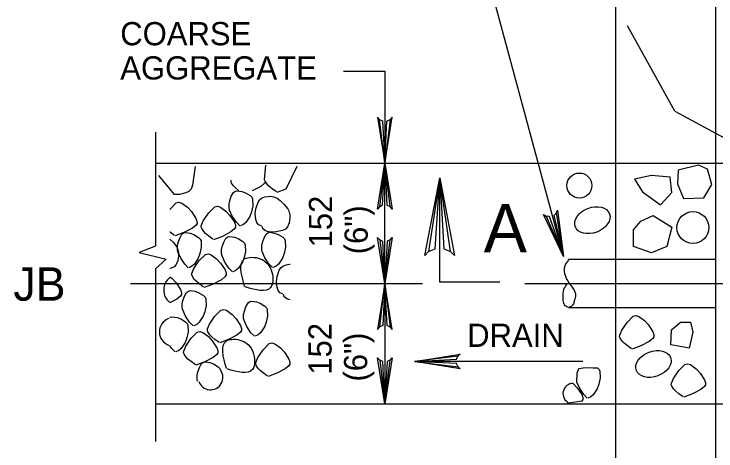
# Model space of a CAD drawing. Extents: x 638455 to 640199, y 298558 to 299152.
# Drawn here: x 638508.8 to 638610.5, y 298960.7 to 299024 of the extents above; entities that cross this region are included whole.
import ezdxf

# ---------------------------------------------------------------- set-up
doc = ezdxf.new("R2010")
doc.units = 0
for name, color, linetype in [('1', 7, 'Continuous'), ('2', 7, 'Continuous'), ('3', 7, 'Continuous')]:
    doc.layers.add(name, color=color, linetype=linetype)

msp = doc.modelspace()

# ---------------------------------------------------------------- linework, layer by layer
at = {"layer": '1'}
for p, q in [((638588.37, 298988.92), (638577.2, 299030.38)), ((638604.5, 299009.98), (638597.64, 299022.33))]:
    msp.add_line(p, q, dxfattribs=at)
for points in [[(638607.93, 299002.12), (638604.99, 299001.42), (638604.91, 298999.41), (638605.77, 298997.32), (638608.71, 298997.39), (638609.87, 298999.33), (638609.25, 299001.58)], [(638602.45, 298996.4), (638604.08, 298998.18), (638603.85, 299000.42), (638601.14, 299000.65), (638598.66, 299000.11), (638599.82, 298998.25)], [(638598.5, 298990.37), (638598.5, 298992.77), (638599.58, 298994.01), (638601.36, 298994.86), (638604.07, 298993.16), (638603.37, 298990.37), (638601.13, 298989.44)], [(638603.93, 298976.13), (638604.02, 298978.28), (638605.31, 298979.4), (638606.77, 298979.4), (638607.12, 298977.94), (638606.6, 298975.62)]]:
    msp.add_lwpolyline(points, close=True, dxfattribs=at)
for centre, radius in [((638590.69, 298999.19), 1.81), ((638607.13, 298993.1), 2.31)]:
    msp.add_circle(centre, radius, dxfattribs=at)
for centre, radius, start, end in [((638532.79, 298984.05), 2.3, 128.3504, 231.6496), ((638531.92, 298978), 2.06, 110.8458, 251.6988), ((638537.27, 298971.41), 1.8, 199.608, 34.7802), ((638589.8, 298969.04), 1.49, 89.5919, 244.8137)]:
    msp.add_arc(centre, radius, start, end, dxfattribs=at)
for centre in [(638592.57, 298994.17), (638601.42, 298973.35)]:
    msp.add_ellipse(centre, major_axis=(-2.48, -0.93), ratio=0.690668, dxfattribs=at)
at = {"layer": '2'}
for p, q in [((638595.94, 299046), (638595.94, 298932.33)), ((638610.47, 298943.57), (638610.47, 299045.2)), ((638556.51, 299015.76), (638562.52, 299015.76)), ((638562.52, 299015.76), (638562.52, 299002.44)), ((638604.5, 299009.98), (638635.74, 298993.07)), ((638529.3, 299006.9), (638529.3, 298990.39)), ((638529.3, 299002.44), (638688.53, 299002.44)), ((638562.52, 298985.02), (638562.52, 299002.44)), ((638570.46, 298985.18), (638570.46, 299000.3)), ((638589.16, 298988.5), (638610.47, 298988.5)), ((638529.3, 298987.13), (638529.3, 298962.13)), ((638525.67, 298985.02), (638567.99, 298985.02)), ((638562.52, 298985.02), (638562.52, 298967.59)), ((638579.18, 298985.18), (638570.46, 298985.18)), ((638582.78, 298985.02), (638777.13, 298985.02)), ((638589.16, 298981.53), (638610.47, 298981.53)), ((638529.3, 298967.59), (638688.53, 298967.59))]:
    msp.add_line(p, q, dxfattribs=at)
for points in [[(638561.72, 299008.77), (638562.18, 299008.54), (638562.52, 299002.44), (638561.72, 299008.77), (638561.45, 299009.1), (638562.52, 299002.44), (638562.82, 299008.53), (638563.27, 299008.75), (638562.52, 299002.44), (638563.58, 299009.1), (638563.27, 299008.75)], [(638545.11, 299000.02), (638545.29, 299002.12)], [(638561.72, 298996.11), (638562.18, 298996.35), (638562.52, 299002.44), (638561.72, 298996.11), (638561.45, 298995.78), (638562.52, 299002.44), (638562.82, 298996.35), (638563.27, 298996.13), (638562.52, 299002.44), (638563.58, 298995.78), (638563.27, 298996.13)], [(638535.06, 299001.95), (638534.68, 298999.23)], [(638549.76, 299001.95), (638548.18, 298998.68)], [(638532.06, 298997.9), (638529.81, 299000.65)], [(638540.26, 298999.77), (638540.26, 298999.98)], [(638545.17, 298999.8), (638545.11, 299000.02)], [(638568.85, 298989.61), (638569.78, 298990), (638570.46, 299000.3), (638568.85, 298989.61), (638568.29, 298989.06), (638570.46, 299000.3), (638571.07, 298990.01), (638572, 298989.63), (638570.46, 299000.3), (638572.61, 298989.06), (638572, 298989.63)], [(638534.68, 298999.23), (638534.45, 298998.66)], [(638540.31, 298999.55), (638540.26, 298999.77)], [(638540.6, 298999.12), (638540.31, 298999.55)], [(638540.89, 298998.83), (638540.6, 298999.12)], [(638544.54, 298999.07), (638543.32, 298998.43)], [(638545.07, 298999.51), (638544.54, 298999.07)], [(638545.22, 298999.76), (638545.07, 298999.51)], [(638545.46, 298999.37), (638545.17, 298999.8)], [(638545.74, 298999.08), (638545.46, 298999.37)], [(638546.19, 298998.71), (638545.74, 298999.08)], [(638533.72, 298998.13), (638532.79, 298997.91)], [(638534.13, 298998.34), (638533.72, 298998.13)], [(638534.45, 298998.66), (638534.13, 298998.34)], [(638540.28, 298997.63), (638540.58, 298998.18)], [(638540.58, 298998.18), (638540.83, 298998.37)], [(638540.83, 298998.37), (638541.14, 298998.44)], [(638541.34, 298998.46), (638540.89, 298998.83)], [(638541.14, 298998.44), (638541.81, 298998.34)], [(638541.81, 298998.34), (638542.34, 298998.14)], [(638542.34, 298998.14), (638543.02, 298997.72)], [(638546.81, 298998.26), (638546.19, 298998.71)], [(638548.18, 298998.68), (638546.89, 298998.2)], [(638532.79, 298997.91), (638532.06, 298997.9)], [(638539.95, 298996.52), (638540.05, 298996.98)], [(638540.05, 298996.98), (638540.28, 298997.63)], [(638543.02, 298997.72), (638543.25, 298997.48)], [(638543.25, 298997.48), (638543.37, 298997.25)], [(638543.37, 298997.25), (638543.4, 298996.27)], [(638544.15, 298996.76), (638544.38, 298997.11)], [(638544.38, 298997.11), (638544.65, 298997.34)], [(638544.65, 298997.34), (638545.15, 298997.54)], [(638545.15, 298997.54), (638545.6, 298997.62)], [(638545.6, 298997.62), (638545.95, 298997.63)], [(638545.95, 298997.63), (638546.46, 298997.56)], [(638546.46, 298997.56), (638546.9, 298997.37)], [(638546.9, 298997.37), (638547.35, 298997.04)], [(638547.35, 298997.04), (638547.96, 298996.46)], [(638531.43, 298995.78), (638532.31, 298996.66)], [(638532.31, 298996.66), (638532.7, 298996.77)], [(638532.7, 298996.77), (638533.13, 298996.64)], [(638533.13, 298996.64), (638533.93, 298996.04)], [(638533.93, 298996.04), (638534.51, 298995.41)], [(638537.01, 298995.22), (638537.88, 298996.1)], [(638537.88, 298996.1), (638538.28, 298996.21)], [(638538.28, 298996.21), (638538.7, 298996.07)], [(638538.7, 298996.07), (638539.51, 298995.48)], [(638539.95, 298995.94), (638539.95, 298996.52)], [(638540.02, 298995.64), (638539.95, 298995.94)], [(638543.4, 298996.27), (638543.21, 298995.38)], [(638543.84, 298995.82), (638544.15, 298996.76)], [(638547.96, 298996.46), (638548.48, 298995.79)], [(638531.4, 298995.73), (638531.43, 298995.78)], [(638534.51, 298995.41), (638535.16, 298994.43)], [(638536.22, 298994.09), (638537.01, 298995.22)], [(638539.51, 298995.48), (638540.08, 298994.85)], [(638540.43, 298994.74), (638540.02, 298995.64)], [(638543.21, 298995.38), (638542.96, 298994.71)], [(638543.76, 298995.12), (638543.84, 298995.82)], [(638543.83, 298994.25), (638543.76, 298995.12)], [(638548.48, 298995.79), (638548.62, 298995.51)], [(638548.62, 298995.51), (638548.76, 298994.92)], [(638548.76, 298994.92), (638548.76, 298994.46)], [(638587.36, 298995.21), (638586.99, 298994.86), (638588.37, 298988.92), (638587.36, 298995.21), (638587.54, 298995.6), (638588.37, 298988.92), (638586.38, 298994.68), (638585.88, 298994.76), (638588.37, 298988.92), (638585.49, 298995.01), (638585.88, 298994.76)], [(638535.16, 298994.43), (638535.31, 298994.02)], [(638535.31, 298994.02), (638535.32, 298993.71)], [(638535.94, 298993.37), (638536.22, 298994.09)], [(638540.08, 298994.85), (638540.73, 298993.87)], [(638541.01, 298993.86), (638540.43, 298994.74)], [(638540.73, 298993.87), (638540.89, 298993.45)], [(638541.51, 298993.34), (638541.01, 298993.86)], [(638542.4, 298993.85), (638542.04, 298993.54)], [(638542.96, 298994.71), (638542.4, 298993.85)], [(638543.97, 298993.84), (638543.83, 298994.25)], [(638548.76, 298994.46), (638548.65, 298993.78)], [(638534.64, 298993.02), (638533.43, 298992.39)], [(638535.17, 298993.46), (638534.64, 298993.02)], [(638535.32, 298993.71), (638535.17, 298993.46)], [(638535.93, 298993.16), (638535.94, 298993.37)], [(638535.99, 298992.94), (638535.93, 298993.16)], [(638536.28, 298992.51), (638535.99, 298992.94)], [(638540.75, 298992.9), (638540.21, 298992.46)], [(638540.89, 298993.15), (638540.75, 298992.9)], [(638540.89, 298993.45), (638540.89, 298993.15)], [(638542.04, 298993.54), (638541.63, 298993.34)], [(638544.22, 298993.5), (638543.97, 298993.84)], [(638544.65, 298993.34), (638544.22, 298993.5)], [(638544.87, 298992.9), (638544.73, 298993.29)], [(638545.22, 298992.64), (638544.87, 298992.9)], [(638548.11, 298992.89), (638547.69, 298992.67)], [(638548.42, 298993.21), (638548.11, 298992.89)], [(638548.65, 298993.78), (638548.42, 298993.21)], [(638531.44, 298992.42), (638531.4, 298992.45)], [(638532.05, 298991.97), (638531.44, 298992.42)], [(638533.43, 298992.39), (638532.14, 298991.91)], [(638532.82, 298991.58), (638533.11, 298992.13)], [(638533.11, 298992.13), (638533.36, 298992.33)], [(638533.36, 298992.33), (638533.67, 298992.39)], [(638533.67, 298992.39), (638534.34, 298992.29)], [(638534.34, 298992.29), (638534.87, 298992.09)], [(638534.87, 298992.09), (638535.55, 298991.67)], [(638536.56, 298992.22), (638536.28, 298992.51)], [(638537.01, 298991.85), (638536.56, 298992.22)], [(638537.63, 298991.4), (638537.01, 298991.85)], [(638539, 298991.82), (638537.71, 298991.34)], [(638540.21, 298992.46), (638539, 298991.82)], [(638545.02, 298991.6), (638545.32, 298992.15)], [(638545.53, 298992.52), (638545.22, 298992.64)], [(638545.32, 298992.15), (638545.56, 298992.35)], [(638546.03, 298992.44), (638545.53, 298992.52)], [(638545.56, 298992.35), (638545.87, 298992.41)], [(638545.87, 298992.41), (638546.55, 298992.31)], [(638546.76, 298992.46), (638546.03, 298992.44)], [(638546.55, 298992.31), (638547.07, 298992.11)], [(638547.69, 298992.67), (638546.76, 298992.46)], [(638547.07, 298992.11), (638547.75, 298991.69)], [(638531.4, 298991.44), (638531.85, 298991)], [(638531.85, 298991), (638532.36, 298990.34)], [(638532.48, 298990.47), (638532.58, 298990.93)], [(638532.58, 298990.93), (638532.82, 298991.58)], [(638535.55, 298991.67), (638535.78, 298991.43)], [(638535.78, 298991.43), (638535.9, 298991.2)], [(638535.9, 298991.2), (638535.93, 298990.22)], [(638538.98, 298990.35), (638539.22, 298991)], [(638539.22, 298991), (638539.51, 298991.55)], [(638539.51, 298991.55), (638539.76, 298991.75)], [(638539.76, 298991.75), (638540.07, 298991.81)], [(638540.07, 298991.81), (638540.74, 298991.71)], [(638540.74, 298991.71), (638541.27, 298991.51)], [(638541.27, 298991.51), (638541.95, 298991.09)], [(638541.95, 298991.09), (638542.18, 298990.86)], [(638542.18, 298990.86), (638542.3, 298990.62)], [(638544.69, 298990.49), (638544.78, 298990.95)], [(638544.78, 298990.95), (638545.02, 298991.6)], [(638547.75, 298991.69), (638547.98, 298991.45)], [(638547.98, 298991.45), (638548.1, 298991.22)], [(638548.1, 298991.22), (638548.13, 298990.24)], [(638563.31, 298991.34), (638562.85, 298991.11), (638562.52, 298985.02), (638563.31, 298991.34), (638563.59, 298991.67), (638562.52, 298985.02), (638562.22, 298991.1), (638561.77, 298991.33), (638562.52, 298985.02), (638561.46, 298991.67), (638561.77, 298991.33)], [(638529.3, 298990.39), (638526.92, 298989.48), (638530.85, 298988.51), (638529.3, 298987.13)], [(638532.36, 298990.34), (638532.51, 298990.05)], [(638532.48, 298989.89), (638532.48, 298990.47)], [(638532.55, 298989.6), (638532.48, 298989.89)], [(638532.51, 298990.05), (638532.64, 298989.47)], [(638535.93, 298990.22), (638535.74, 298989.33)], [(638538.88, 298989.9), (638538.98, 298990.35)], [(638538.88, 298989.32), (638538.88, 298989.9)], [(638542.3, 298990.62), (638542.33, 298989.65)], [(638544.68, 298989.91), (638544.69, 298990.49)], [(638544.75, 298989.62), (638544.68, 298989.91)], [(638548.13, 298990.24), (638547.95, 298989.35)], [(638532.65, 298989), (638532.54, 298988.32)], [(638532.96, 298988.69), (638532.55, 298989.6)], [(638532.64, 298989.47), (638532.65, 298989)], [(638535.74, 298989.33), (638535.49, 298988.66)], [(638535.65, 298988.31), (638536.53, 298989.19)], [(638536.53, 298989.19), (638536.92, 298989.3)], [(638536.92, 298989.3), (638537.35, 298989.16)], [(638537.35, 298989.16), (638538.15, 298988.56)], [(638538.95, 298989.02), (638538.88, 298989.32)], [(638539.36, 298988.11), (638538.95, 298989.02)], [(638542.33, 298989.65), (638542.14, 298988.75)], [(638545.16, 298988.71), (638544.75, 298989.62)], [(638547.95, 298989.35), (638547.69, 298988.68)], [(638532.31, 298987.75), (638531.99, 298987.43)], [(638532.54, 298988.32), (638532.31, 298987.75)], [(638533.54, 298987.81), (638532.96, 298988.69)], [(638534.04, 298987.29), (638533.54, 298987.81)], [(638534.93, 298987.8), (638534.57, 298987.49)], [(638534.87, 298987.17), (638535.65, 298988.31)], [(638535.49, 298988.66), (638534.93, 298987.8)], [(638538.15, 298988.56), (638538.73, 298987.94)], [(638538.73, 298987.94), (638539.37, 298986.96)], [(638539.94, 298987.23), (638539.36, 298988.11)], [(638541.89, 298988.09), (638541.32, 298987.23)], [(638542.14, 298988.75), (638541.89, 298988.09)], [(638545.74, 298987.83), (638545.16, 298988.71)], [(638546.25, 298987.31), (638545.74, 298987.83)], [(638547.13, 298987.82), (638546.77, 298987.51)], [(638547.69, 298988.68), (638547.13, 298987.82)], [(638548.24, 298987.71), (638548.69, 298987.78)], [(638548.69, 298987.78), (638548.82, 298987.79)], [(638531.58, 298987.22), (638531.4, 298987.18)], [(638531.99, 298987.43), (638531.58, 298987.22)], [(638534.57, 298987.49), (638534.16, 298987.29)], [(638534.58, 298986.46), (638534.87, 298987.17)], [(638539.37, 298986.96), (638539.53, 298986.54)], [(638540.44, 298986.71), (638539.94, 298987.23)], [(638540.97, 298986.91), (638540.55, 298986.71)], [(638541.32, 298987.23), (638540.97, 298986.91)], [(638546.77, 298987.51), (638546.36, 298987.31)], [(638546.93, 298985.99), (638547.23, 298986.92)], [(638547.23, 298986.92), (638547.46, 298987.28)], [(638547.46, 298987.28), (638547.73, 298987.51)], [(638547.73, 298987.51), (638548.24, 298987.71)], [(638531.4, 298985.97), (638531.7, 298985.74)], [(638531.7, 298985.74), (638532.28, 298985.11)], [(638534.57, 298986.25), (638534.58, 298986.46)], [(638534.64, 298986.03), (638534.57, 298986.25)], [(638534.92, 298985.6), (638534.64, 298986.03)], [(638539.39, 298985.99), (638538.86, 298985.54)], [(638539.54, 298986.24), (638539.39, 298985.99)], [(638539.53, 298986.54), (638539.54, 298986.24)], [(638546.85, 298985.29), (638546.93, 298985.99)], [(638532.28, 298985.11), (638532.93, 298984.13)], [(638535.21, 298985.32), (638534.92, 298985.6)], [(638535.66, 298984.95), (638535.21, 298985.32)], [(638536.27, 298984.49), (638535.66, 298984.95)], [(638537.64, 298984.91), (638536.36, 298984.44)], [(638538.86, 298985.54), (638537.64, 298984.91)], [(638546.91, 298984.41), (638546.85, 298985.29)], [(638563.31, 298978.69), (638562.85, 298978.92), (638562.52, 298985.02), (638563.31, 298978.69), (638563.59, 298978.36), (638562.52, 298985.02), (638562.22, 298978.93), (638561.77, 298978.71), (638562.52, 298985.02), (638561.46, 298978.36), (638561.77, 298978.71)], [(638532.93, 298984.13), (638533.08, 298983.71)], [(638533.08, 298983.71), (638533.09, 298983.41)], [(638533.52, 298983.16), (638533.81, 298983.71)], [(638533.81, 298983.71), (638534.06, 298983.91)], [(638534.06, 298983.91), (638534.37, 298983.97)], [(638534.37, 298983.97), (638535.04, 298983.87)], [(638535.04, 298983.87), (638535.57, 298983.67)], [(638547.05, 298984), (638546.91, 298984.41)], [(638547.31, 298983.66), (638547.05, 298984)], [(638532.41, 298982.72), (638531.4, 298982.19)], [(638532.94, 298983.16), (638532.41, 298982.72)], [(638533.09, 298983.41), (638532.94, 298983.16)], [(638533.28, 298982.51), (638533.52, 298983.16)], [(638535.57, 298983.67), (638536.25, 298983.25)], [(638536.25, 298983.25), (638536.48, 298983.02)], [(638536.48, 298983.02), (638536.6, 298982.79)], [(638536.6, 298982.79), (638536.63, 298981.81)], [(638547.73, 298983.51), (638547.31, 298983.66)], [(638547.95, 298983.07), (638547.82, 298983.45)], [(638548.3, 298982.8), (638547.95, 298983.07)], [(638548.62, 298982.69), (638548.3, 298982.8)], [(638548.82, 298982.65), (638548.62, 298982.69)], [(638533.18, 298982.06), (638533.28, 298982.51)], [(638533.18, 298981.48), (638533.18, 298982.06)], [(638536.63, 298981.81), (638536.44, 298980.92)], [(638542.4, 298981.64), (638542.7, 298982.19)], [(638542.7, 298982.19), (638542.95, 298982.38)], [(638542.95, 298982.38), (638543.26, 298982.45)], [(638543.26, 298982.45), (638543.93, 298982.35)], [(638543.93, 298982.35), (638544.46, 298982.15)], [(638544.46, 298982.15), (638545.14, 298981.73)], [(638545.14, 298981.73), (638545.37, 298981.49)], [(638533.25, 298981.18), (638533.18, 298981.48)], [(638533.66, 298980.27), (638533.25, 298981.18)], [(638536.44, 298980.92), (638536.19, 298980.25)], [(638537.89, 298980.27), (638538.77, 298981.15)], [(638538.77, 298981.15), (638539.17, 298981.25)], [(638539.17, 298981.25), (638539.59, 298981.12)], [(638539.59, 298981.12), (638540.39, 298980.52)], [(638542.07, 298980.53), (638542.17, 298980.99)], [(638542.17, 298980.99), (638542.4, 298981.64)], [(638545.37, 298981.49), (638545.49, 298981.26)], [(638545.49, 298981.26), (638545.52, 298980.29)], [(638531.4, 298980.06), (638531.47, 298980.12)], [(638531.47, 298980.12), (638531.78, 298980.18)], [(638531.78, 298980.18), (638532.45, 298980.08)], [(638532.45, 298980.08), (638532.98, 298979.88)], [(638532.98, 298979.88), (638533.66, 298979.46)], [(638534.24, 298979.4), (638533.66, 298980.27)], [(638536.19, 298980.25), (638535.63, 298979.39)], [(638537.11, 298979.13), (638537.89, 298980.27)], [(638540.39, 298980.52), (638540.97, 298979.89)], [(638540.97, 298979.89), (638541.61, 298978.91)], [(638542.07, 298979.95), (638542.07, 298980.53)], [(638542.14, 298979.66), (638542.07, 298979.95)], [(638542.55, 298978.75), (638542.14, 298979.66)], [(638545.52, 298980.29), (638545.33, 298979.39)], [(638597.6, 298979.37), (638598.48, 298980.25)], [(638598.48, 298980.25), (638598.87, 298980.35)], [(638598.87, 298980.35), (638599.3, 298980.22)], [(638599.3, 298980.22), (638600.1, 298979.62)], [(638600.1, 298979.62), (638600.68, 298979)], [(638533.66, 298979.46), (638533.89, 298979.23)], [(638533.89, 298979.23), (638534.01, 298979)], [(638534.01, 298979), (638534.04, 298978.02)], [(638534.74, 298978.87), (638534.24, 298979.4)], [(638535.27, 298979.07), (638534.86, 298978.87)], [(638535.63, 298979.39), (638535.27, 298979.07)], [(638536.83, 298978.41), (638537.11, 298979.13)], [(638541.61, 298978.91), (638541.77, 298978.5)], [(638543.13, 298977.87), (638542.55, 298978.75)], [(638545.08, 298978.72), (638544.52, 298977.86)], [(638545.33, 298979.39), (638545.08, 298978.72)], [(638596.82, 298978.23), (638597.6, 298979.37)], [(638600.68, 298979), (638601.32, 298978.01)], [(638534.04, 298978.02), (638533.85, 298977.13)], [(638534.46, 298977.06), (638535.33, 298977.94)], [(638535.33, 298977.94), (638535.73, 298978.04)], [(638535.73, 298978.04), (638536.15, 298977.91)], [(638536.15, 298977.91), (638536.96, 298977.31)], [(638536.82, 298978.2), (638536.83, 298978.41)], [(638536.88, 298977.99), (638536.82, 298978.2)], [(638537.17, 298977.55), (638536.88, 298977.99)], [(638541.63, 298977.94), (638541.1, 298977.5)], [(638541.78, 298978.19), (638541.63, 298977.94)], [(638541.77, 298978.5), (638541.78, 298978.19)], [(638543.63, 298977.35), (638543.13, 298977.87)], [(638544.52, 298977.86), (638544.16, 298977.55)], [(638596.54, 298977.52), (638596.82, 298978.23)], [(638601.32, 298978.01), (638601.48, 298977.6)], [(638601.48, 298977.6), (638601.49, 298977.29)], [(638533.85, 298977.13), (638533.59, 298976.46)], [(638533.68, 298975.92), (638534.46, 298977.06)], [(638536.96, 298977.31), (638537.53, 298976.68)], [(638537.45, 298977.27), (638537.17, 298977.55)], [(638537.9, 298976.9), (638537.45, 298977.27)], [(638537.53, 298976.68), (638538.18, 298975.7)], [(638538.52, 298976.45), (638537.9, 298976.9)], [(638539.89, 298976.87), (638538.6, 298976.39)], [(638541.1, 298977.5), (638539.89, 298976.87)], [(638544.16, 298977.55), (638543.75, 298977.35)], [(638596.52, 298977.31), (638596.54, 298977.52)], [(638596.58, 298977.09), (638596.52, 298977.31)], [(638596.88, 298976.65), (638596.58, 298977.09)], [(638597.16, 298976.37), (638596.88, 298976.65)], [(638600.8, 298976.6), (638599.59, 298975.97)], [(638601.34, 298977.05), (638600.8, 298976.6)], [(638601.49, 298977.29), (638601.34, 298977.05)], [(638531.65, 298975.61), (638531.4, 298975.99)], [(638532.15, 298975.08), (638531.65, 298975.61)], [(638533.03, 298975.6), (638532.67, 298975.29)], [(638533.59, 298976.46), (638533.03, 298975.6)], [(638533.39, 298975.21), (638533.68, 298975.92)], [(638538.18, 298975.7), (638538.34, 298975.29)], [(638544.89, 298975.41), (638545.77, 298976.29)], [(638545.77, 298976.29), (638546.16, 298976.39)], [(638546.16, 298976.39), (638546.59, 298976.26)], [(638546.59, 298976.26), (638547.39, 298975.66)], [(638547.39, 298975.66), (638547.97, 298975.04)], [(638597.6, 298976), (638597.16, 298976.37)], [(638598.22, 298975.55), (638597.6, 298976)], [(638599.59, 298975.97), (638598.31, 298975.49)], [(638532.67, 298975.29), (638532.26, 298975.08)], [(638533.38, 298974.99), (638533.39, 298975.21)], [(638533.44, 298974.78), (638533.38, 298974.99)], [(638533.73, 298974.34), (638533.44, 298974.78)], [(638538.2, 298974.74), (638537.66, 298974.29)], [(638538.34, 298974.98), (638538.2, 298974.74)], [(638538.34, 298975.29), (638538.34, 298974.98)], [(638544.11, 298974.27), (638544.89, 298975.41)], [(638547.97, 298975.04), (638548.61, 298974.06)], [(638573.12, 298972.93), (638572.88, 298973.39), (638566.79, 298973.72), (638573.12, 298972.93), (638573.44, 298972.65), (638566.79, 298973.72), (638572.88, 298974.02), (638573.1, 298974.48), (638566.79, 298973.72), (638573.44, 298974.78), (638573.1, 298974.48)], [(638534.01, 298974.06), (638533.73, 298974.34)], [(638534.46, 298973.69), (638534.01, 298974.06)], [(638535.08, 298973.23), (638534.46, 298973.69)], [(638536.45, 298973.66), (638535.16, 298973.18)], [(638535.95, 298973.4), (638536.2, 298973.6)], [(638536.2, 298973.6), (638536.51, 298973.66)], [(638537.66, 298974.29), (638536.45, 298973.66)], [(638536.51, 298973.66), (638537.18, 298973.56)], [(638537.18, 298973.56), (638537.71, 298973.36)], [(638543.81, 298973.35), (638543.82, 298973.56)], [(638543.82, 298973.56), (638544.11, 298974.27)], [(638548.61, 298974.06), (638548.77, 298973.64)], [(638548.77, 298973.64), (638548.78, 298973.33)], [(638563.31, 298973.92), (638562.85, 298973.69), (638562.52, 298967.59), (638563.31, 298973.92), (638563.59, 298974.25), (638562.52, 298967.59), (638562.22, 298973.68), (638561.77, 298973.9), (638562.52, 298967.59), (638561.46, 298974.25), (638561.77, 298973.9)], [(638591.19, 298973.72), (638573.76, 298973.72), (638566.79, 298973.72)], [(638535.42, 298972.2), (638535.66, 298972.85)], [(638535.66, 298972.85), (638535.95, 298973.4)], [(638537.71, 298973.36), (638538.39, 298972.94)], [(638538.39, 298972.94), (638538.62, 298972.71)], [(638538.62, 298972.71), (638538.74, 298972.47)], [(638543.87, 298973.13), (638543.81, 298973.35)], [(638544.16, 298972.7), (638543.87, 298973.13)], [(638544.45, 298972.41), (638544.16, 298972.7)], [(638548.09, 298972.64), (638546.88, 298972.01)], [(638548.63, 298973.09), (638548.09, 298972.64)], [(638548.78, 298973.33), (638548.63, 298973.09)], [(638590.35, 298972.03), (638590.59, 298972.68)], [(638590.59, 298972.68), (638591.55, 298972.83)], [(638591.55, 298972.83), (638592.63, 298972.81)], [(638592.67, 298972.81), (638593.32, 298972.77)], [(638593.32, 298972.77), (638593.55, 298972.53)], [(638593.55, 298972.53), (638593.67, 298972.3)], [(638605.08, 298972.4), (638605.96, 298973.28)], [(638605.96, 298973.28), (638606.35, 298973.38)], [(638606.35, 298973.38), (638606.78, 298973.25)], [(638606.78, 298973.25), (638607.58, 298972.65)], [(638607.58, 298972.65), (638608.16, 298972.03)], [(638535.32, 298971.75), (638535.42, 298972.2)], [(638535.32, 298971.17), (638535.32, 298971.75)], [(638544.89, 298972.04), (638544.45, 298972.41)], [(638545.51, 298971.59), (638544.89, 298972.04)], [(638546.88, 298972.01), (638545.6, 298971.53)], [(638590.33, 298970.7), (638590.35, 298972.03)], [(638593.67, 298972.3), (638593.7, 298971.32)], [(638604.3, 298971.26), (638605.08, 298972.4)], [(638608.16, 298972.03), (638608.81, 298971.05)], [(638535.39, 298970.87), (638535.32, 298971.17)], [(638589.81, 298970.53), (638590.39, 298969.9)], [(638590.73, 298969.79), (638590.32, 298970.69)], [(638593.7, 298971.32), (638593.52, 298970.43)], [(638604, 298970.34), (638604.02, 298970.55)], [(638604.02, 298970.55), (638604.3, 298971.26)], [(638608.81, 298971.05), (638608.96, 298970.63)], [(638608.96, 298970.63), (638608.97, 298970.32)], [(638590.39, 298969.9), (638591.03, 298968.92)], [(638591.31, 298968.91), (638590.73, 298969.79)], [(638593.26, 298969.76), (638592.7, 298968.9)], [(638593.52, 298970.43), (638593.26, 298969.76)], [(638604.07, 298970.12), (638604, 298970.34)], [(638604.36, 298969.69), (638604.07, 298970.12)], [(638604.64, 298969.4), (638604.36, 298969.69)], [(638608.29, 298969.63), (638607.07, 298969)], [(638608.82, 298970.08), (638608.29, 298969.63)], [(638608.97, 298970.32), (638608.82, 298970.08)], [(638591.03, 298968.92), (638591.19, 298968.5)], [(638591.19, 298968.5), (638591.2, 298968.2)], [(638591.82, 298968.39), (638591.31, 298968.91)], [(638592.34, 298968.59), (638591.93, 298968.39)], [(638592.7, 298968.9), (638592.34, 298968.59)], [(638605.09, 298969.03), (638604.64, 298969.4)], [(638605.7, 298968.58), (638605.09, 298969.03)], [(638607.07, 298969), (638605.79, 298968.52)], [(638591.05, 298967.95), (638589.16, 298967.69)], [(638591.2, 298968.2), (638591.05, 298967.95)]]:
    msp.add_lwpolyline(points, dxfattribs=at)
for points in [[(638542.21, 298984.55), (638542.21, 298988.55), (638544.46, 298988.58), (638546.03, 298987), (638545.98, 298984.41), (638542.29, 298984.5)], [(638589.16, 298988.5), (638588.5, 298987.22), (638588.62, 298986.19), (638589.16, 298985.1), (638590.14, 298983.34), (638589.95, 298982.49), (638589.75, 298981.91), (638589.16, 298981.53)], [(638589.16, 298981.53), (638588.62, 298981.78), (638588.38, 298982.32), (638588.32, 298983.11), (638588.38, 298983.83), (638588.5, 298984.31), (638588.8, 298984.8), (638588.92, 298984.98), (638589.11, 298985.04)], [(638539.57, 298972.68), (638539.57, 298976.68), (638541.83, 298976.71), (638543.4, 298975.13), (638543.34, 298972.54), (638539.66, 298972.63)]]:
    msp.add_spline(points, degree=3, dxfattribs=at)

# ---------------------------------------------------------------- texts
at = {"layer": '3'}
for s, height, p in [('COARSE', 3.36, (638524.2, 299019.5)), ('AGGREGATE', 3.36, (638524.2, 299014.54)), ('A', 7, (638576.84, 298989.53)), ('L JB', 4.838, (638503.33, 298982.51)), ('DRAIN', 3.36, (638574.44, 298975.82))]:
    msp.add_text(s, height=height, dxfattribs=at).set_placement(p)
for s, p in [('152', (638554.88, 298990.22)), ('(6")', (638560.04, 298989.23)), ('152', (638554.8, 298971.79)), ('(6")', (638559.96, 298970.8))]:
    msp.add_text(s, height=3.36, rotation=90, dxfattribs=at).set_placement(p)

doc.saveas('drawing.dxf')
